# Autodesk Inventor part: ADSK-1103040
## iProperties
Shininess: 11.0
Compacted: True
Length Units: 11269
Angle Units: 11279
Time Units: 11290
Mass Units: 11286
Length Display Precision: 2
Angle Display Precision: 2
Created: 2000-07
Part Number: ADSK-1103040
Document SubType Name: Modeling
Description: ENGINE  CASE - REAR
Mass: 106.441 g
Surface Area: 158.116 cm^2
Volume: 13.1734 cm^3
Density: 8.08 g/cm^3
Material: Stainless Steel
Density: 0.0
Volumn: 0.0
Area: 0.0
PropertySet Name: Model Information
Control State: 0
Master: False
Checked Out: False
Author: Autodesk, Inc.
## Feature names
1. Fillet48
2. Fillet53
3. Fillet49
4. Fillet50
5. Fillet51
6. Fillet52
7. Split2
8. Extrusion38
9. Mirror3
10. Fillet54
11. Fillet58
12. Fillet55
13. Fillet57
14. Mirror4
15. Fillet59
16. Extrusion39
17. Fillet60
18. Fillet77
19. Fillet78
20. Fillet79
21. Fillet80
22. Split4
23. Split7
24. Fillet64
25. Fillet65
26. Extrusion40
27. Fillet66
28. Fillet67
29. Fillet68
30. Extrusion41
31. Hole5
32. Chamfer2
33. Fillet76
34. Extrusion42
35. Hole6
36. Fillet69
37. Mirror5
38. Fillet70
39. Fillet71
40. Revolution3
41. Fillet72
42. Fillet73
43. Mirror6
44. Fillet74
45. Fillet75
46. Extrusion43
47. Fillet81
48. Mirror7
49. Revolution4
